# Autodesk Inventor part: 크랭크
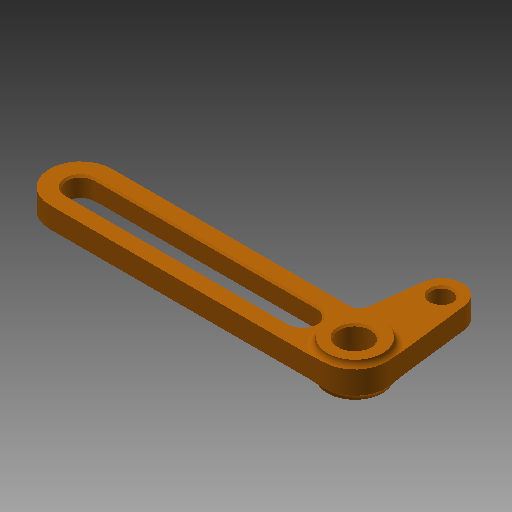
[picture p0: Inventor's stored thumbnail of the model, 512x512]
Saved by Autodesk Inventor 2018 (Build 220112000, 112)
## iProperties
Created: 2019-09
Part Number: 크랭크
Material: 알루미늄 6061
Document SubType Name: Modeling
Designer: mduedu
Density: 2.71 g/cm^3
Appearance: 주황색
Mass: 23.0159 g
Surface Area: 54.7149 cm^2
Volume: 8.49295 cm^3
Author: mduedu
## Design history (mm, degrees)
sketch "스케치1"
  geometry: L1 (0, 0)-(79, 0); L2 (0, 9)-(79, 9); L3 (10.637, -9)-(79, -9); L4 (0, 0)-(0, -25); L5 (-8.935, -1.08)-(-5.957, -25.72); L6 (7.659, -11.64)-(5.957, -25.72); L7 (79, -4)-(15, -4); L8 (15, 4)-(79, 4); C1 r 3 at (0, -25); A1 r 9 centre (0, 0) between (0, 9) and (-8.935, -1.08); A2 r 9 centre (79, 0) between (79, -9) and (79, 9); A3 r 6 centre (0, -25) between (-5.957, -25.72) and (5.957, -25.72); A4 r 3 centre (10.637, -12) between (10.637, -9) and (7.659, -11.64); A5 r 4 centre (79, 0) between (79, -4) and (79, 4); A6 r 4 centre (15, 0) between (15, -4) and (15, 4); 1 further point
  constraints: 16 end point, 13 point on circle, 12 tangent, 7 centre point, 5 coincident, 3 horizontal, 2 point on line, 1 equal radius, 1 perpendicular, 1 other
  dimensions: "d0" = 79 distance of L1.start L1.end; "d2" = 25 distance of L1.start L4.end; "d3" = 3 radius of A4; "d4" = 9 radius of A1; "d5" = 6 radius of A3; "d6" = 8 diameter of A5; "d7" = 64 distance of A6.centre L1.end; "d8" = 6 diameter of C1
extrude "돌출1" new body sketch "스케치1" stored distance "d9" = 6; taper "d10" = 0 deg
sketch "스케치2"
  geometry: C1 r 8 at (0, 0); 1 further point
  constraints: 1 centre point, 1 coincident
  dimensions: "d11" = 16 diameter of C1
extrude "돌출2" join sketch "스케치2" stored distance "d12" = 10; taper "d13" = 0 deg
sketch "스케치3"
  geometry: C1 r 4.5 at (0, 0); 1 further point
  constraints: 1 centre point, 1 coincident
  dimensions: "d14" = 9 diameter of C1
extrude "돌출3" cut sketch "스케치3" extent not by distance; stored distance "d15" = 10; taper "d16" = 0 deg
fillet "모깎기1" dims "d17" = 2
chamfer "모따기1" distance "d18" = 0.5; stored, may be unused: second distance "d19" = 2, angle "d20" = 45 deg
node "솔리드1"
